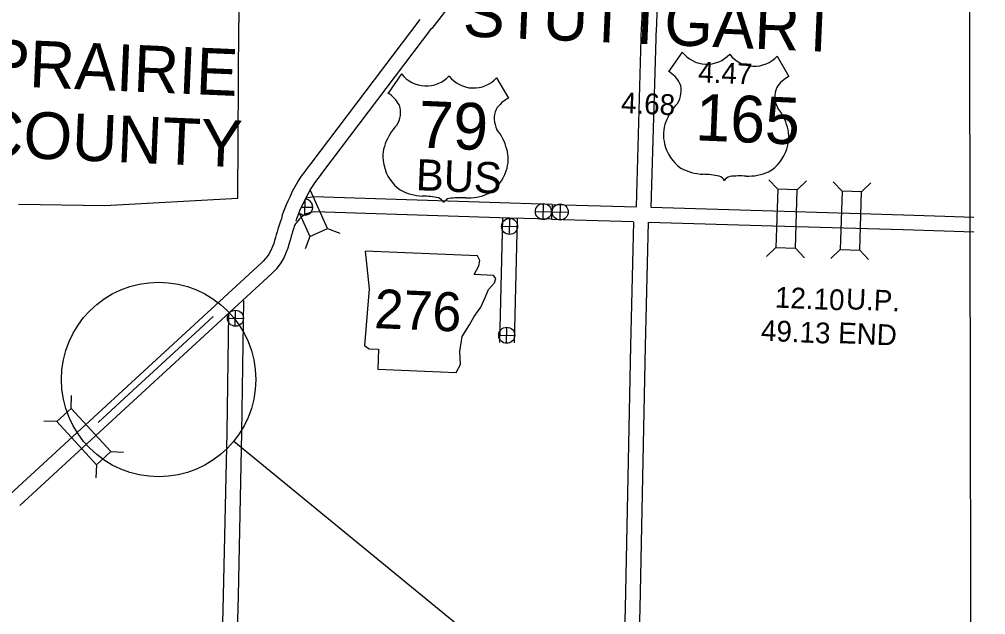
# Model space of a CAD drawing. Extents: x 1196286 to 1268366, y 2040822 to 2082115.
# Drawn here: x 1203681 to 1207611, y 2076830 to 2079249 of the extents above; entities that cross this region are included whole.
import ezdxf

# ---------------------------------------------------------------- set-up
doc = ezdxf.new("R2010")
doc.units = 0
for name, color, linetype in [('55', 7, 'Continuous'), ('Level 100', 7, 'Continuous'), ('Level 70', 7, 'Continuous'), ('Level 78', 7, 'Continuous'), ('Level 8', 7, 'Continuous'), ('Level 80', 7, 'Continuous'), ('Level 82', 7, 'Continuous'), ('Level 84', 7, 'Continuous'), ('Level 87', 7, 'Continuous'), ('Level 95', 7, 'Continuous'), ('Level 96', 7, 'Continuous'), ('Level 97', 7, 'Continuous'), ('Level 98', 7, 'Continuous')]:
    doc.layers.add(name, color=color, linetype=linetype)

msp = doc.modelspace()

# ---------------------------------------------------------------- linework, layer by layer
at = {"layer": '55'}
for points in [[(1207474.9, 2081607.9), (1206837.9, 2081629.8), (1206310.3, 2081646.8), (1205782.4, 2081667.1), (1205202.6, 2081688.7), (1204632, 2081707.9), (1204616.8, 2081158.3), (1204597.1, 2080598.6), (1204583.7, 2080115.1), (1204568.5, 2079583.1), (1204573.6, 2079234.1)], [(1203677.3, 2078498.2), (1204029.1, 2078492.6), (1204569.7, 2078521.8), (1204573.6, 2079234.1)]]:
    msp.add_lwpolyline(points, dxfattribs=at)
at = {"layer": 'Level 100'}
for p, q in [((1204841.8, 2078453.2), (1204843.1, 2078518.3)), ((1204831.6, 2078486), (1204875, 2078485.1)), ((1205811.8, 2078435), (1205813.1, 2078500.1)), ((1205880.3, 2078433.6), (1205881.6, 2078498.7)), ((1205674.3, 2078375), (1205675.6, 2078440.1)), ((1205779.9, 2078468.2), (1205845, 2078466.9)), ((1205848.4, 2078466.8), (1205913.5, 2078465.5)), ((1205642.4, 2078408.2), (1205707.5, 2078406.9)), ((1204559.5, 2078001.8), (1204560.8, 2078066.9)), ((1204527.6, 2078035), (1204592.7, 2078033.7)), ((1205630.8, 2077965.6), (1205695.9, 2077964.3)), ((1205662.7, 2077932.4), (1205664, 2077997.5))]:
    msp.add_line(p, q, dxfattribs=at)
for centre in [(1205812.5, 2078467.5), (1205880.9, 2078466.1), (1205675, 2078407.6), (1204560.2, 2078034.3), (1205663.3, 2077965)]:
    msp.add_circle(centre, 32.6, dxfattribs=at)
msp.add_arc((1204842.4, 2078485.7), 32.6, 230.3311, 84.3995, dxfattribs=at)
at = {"layer": 'Level 78'}
msp.add_lwpolyline([(1205088.3, 2078307.1), (1205104.6, 2078154), (1205084.6, 2077923.7), (1205104.3, 2077910.2), (1205142.4, 2077908.6), (1205138.9, 2077827.4), (1205458.3, 2077813.8), (1205475, 2077846.1), (1205472.2, 2077899.5), (1205482.4, 2077960), (1205512.3, 2078007), (1205531.6, 2078041.8), (1205558.6, 2078078.7), (1205575.5, 2078118.6), (1205589.6, 2078151), (1205613.6, 2078177.9), (1205619.5, 2078195.5), (1205609.9, 2078208.6), (1205531.3, 2078211.9), (1205550.5, 2078246.7), (1205554.1, 2078269.4), (1205544.3, 2078287.4)], close=True, dxfattribs=at)
at = {"layer": 'Level 8'}
msp.add_line((1204553.5, 2077535), (1208376.7, 2074405.8), dxfattribs=at)
msp.add_lwpolyline([(1196285.8, 2082114.9), (1207540.7, 2082114.9), (1207563, 2069523.3), (1196285.8, 2069523.3)], close=True, dxfattribs=at)
msp.add_lwpolyline([(1204002, 2077610.5), (1204109.1, 2077709), (1204396.5, 2077973.5), (1204469.5, 2078041.3)], dxfattribs=at)
msp.add_circle((1204247.6, 2077785.3), 395.3, dxfattribs=at)
at = {"layer": 'Level 80'}
for p, q in [((1206377.4, 2079116), (1206322.1, 2079038)), ((1206763.1, 2079099.5), (1206811.5, 2079017)), ((1205236, 2079027.3), (1205180.7, 2078949.3)), ((1205621.8, 2079010.8), (1205670.2, 2078928.3))]:
    msp.add_line(p, q, dxfattribs=at)
for centre, radius, start, end in [((1206477.5, 2079193.1), 126.4, 217.623, 317.2181), ((1206670, 2079184.9), 126.4, 217.8778, 317.4729), ((1205336.1, 2079104.5), 126.4, 217.623, 317.2181), ((1206249.3, 2078924.4), 134.9, 28.3289, 57.5362), ((1205528.6, 2079096.2), 126.4, 217.8778, 317.4729), ((1206280.5, 2078958.7), 92.5, 326.3584, 18.7587), ((1206874.3, 2078897.7), 134.9, 117.5597, 146.767), ((1205108, 2078835.7), 134.9, 28.3289, 57.5362), ((1206846.2, 2078934.5), 92.5, 156.3372, 208.7375), ((1205733, 2078809), 134.9, 117.5597, 146.767), ((1206514, 2078759), 215.7, 136.5044, 160.2393), ((1205139.1, 2078870), 92.5, 326.3584, 18.7587), ((1205704.9, 2078845.8), 92.5, 156.3372, 208.7375), ((1206596.5, 2078755.4), 215.7, 14.8566, 38.5915), ((1206443.6, 2078779.7), 142.6, 158.5056, 194.9298), ((1205372.6, 2078670.3), 215.7, 136.5044, 160.2393), ((1205455.1, 2078666.7), 215.7, 14.8566, 38.5915), ((1206668.4, 2078770), 142.6, 340.1661, 16.5903), ((1205302.2, 2078691), 142.6, 158.5056, 194.9298), ((1205527.1, 2078681.4), 142.6, 340.1661, 16.5903), ((1206466.8, 2078779.1), 165, 192.6554, 234.6791), ((1206645.2, 2078771.4), 165, 300.4168, 342.4405), ((1205325.4, 2078690.4), 165, 192.6554, 234.6791), ((1205503.9, 2078682.8), 165, 300.4168, 342.4405), ((1206472.1, 2078830.9), 211.8, 241.625, 267.1258), ((1206451.3, 2078231.5), 388, 78.7421, 88.5018), ((1206514.7, 2078576.9), 37.2, 25.5822, 70.5343), ((1206580.2, 2078574.1), 37.2, 104.5616, 149.5137), ((1206613.8, 2078224.5), 388, 86.5941, 96.3538), ((1206644.4, 2078823.5), 211.8, 267.9701, 293.4709), ((1205330.7, 2078742.2), 211.8, 241.625, 267.1258), ((1205310, 2078142.8), 388, 78.7421, 88.5018), ((1205373.3, 2078488.2), 37.2, 25.5822, 70.5343), ((1205438.9, 2078485.4), 37.2, 104.5616, 149.5137), ((1205472.5, 2078135.8), 388, 86.5941, 96.3538), ((1205503, 2078734.8), 211.8, 267.9701, 293.4709)]:
    msp.add_arc(centre, radius, start, end, dxfattribs=at)
at = {"layer": 'Level 84'}
for points in [[(1206222.9, 2079653.8), (1206076.9, 2079554.7), (1206042, 2079537.7), (1206024.4, 2079533.2), (1206007.5, 2079529.9), (1205989.9, 2079529.5), (1205962, 2079530.1), (1205937.7, 2079530.6), (1205718.3, 2079537.8), (1205668.6, 2079538.7), (1205657.3, 2079537.3), (1205642.7, 2079535.6), (1205627.8, 2079529.9), (1205616.3, 2079525.1), (1205605, 2079518.8), (1205594.8, 2079512.6), (1205585.3, 2079504.7), (1205572.1, 2079488.7), (1205561, 2079473.6), (1205358.7, 2079212.3)], [(1206217.3, 2079437.4), (1206212.1, 2079219.2)], [(1206277.2, 2079431.3), (1206272.1, 2079217.8)], [(1204748.1, 2078437.4), (1204750.9, 2078455.9), (1204759.6, 2078476.3), (1204767.5, 2078496), (1204774.9, 2078511.8), (1204782.2, 2078527.8), (1204792.7, 2078550), (1204814.1, 2078588.1), (1204829.4, 2078611.3), (1204843.1, 2078630.2), (1204853.8, 2078644.5), (1204868.4, 2078663.6), (1205311.1, 2079248.7)], [(1204807.4, 2078428.4), (1204809.1, 2078439.4), (1204815, 2078453.3), (1204822.6, 2078472.1), (1204829.4, 2078486.7), (1204836.6, 2078502.4), (1204846.1, 2078522.4), (1204865.3, 2078556.8), (1204878.8, 2078577.2), (1204891.5, 2078594.7), (1204901.6, 2078608.3), (1204916.1, 2078627.2), (1205358.9, 2079212.5)], [(1206190.6, 2078487.7), (1206212.1, 2079219.4)], [(1206250.5, 2078483.9), (1206272.1, 2079217.6)], [(1205847.8, 2078496.5), (1205677.3, 2078501.3), (1204876.9, 2078527.2), (1204862.9, 2078524.4), (1204853, 2078522.9), (1204845.5, 2078520.8)], [(1205847.8, 2078496.5), (1205846, 2078436.5)], [(1204746.9, 2078438), (1204744.6, 2078433.5), (1204739.6, 2078415.9), (1204735.2, 2078403.8), (1204733, 2078396), (1204729.7, 2078385.5), (1204726.2, 2078372.7), (1204722.8, 2078362.5), (1204719, 2078350.6), (1204715.6, 2078337.7), (1204710.9, 2078325.5), (1204704.4, 2078309.6), (1204695.5, 2078294.9), (1204693.5, 2078290.6), (1204689.3, 2078285.4), (1204685.7, 2078280), (1204682.6, 2078276.6), (1204672.4, 2078266.1), (1204665.8, 2078258.9), (1203642.8, 2077318.1)], [(1205846, 2078436.5), (1205675.5, 2078441.3), (1204881.9, 2078467), (1204873.3, 2078465.3), (1204865.5, 2078464.1), (1204857.5, 2078461.9), (1204849.4, 2078458.9), (1204842.2, 2078455.1), (1204838.6, 2078453.5), (1204835.4, 2078451), (1204829.2, 2078445.9), (1204820, 2078437.8), (1204814.8, 2078431.7), (1204806.8, 2078421.3), (1204803.5, 2078417.1), (1204802.4, 2078414.6), (1204800.7, 2078411.3), (1204796.7, 2078397.5), (1204792.4, 2078385.5), (1204790.5, 2078378.9), (1204787.3, 2078368.4), (1204783.6, 2078355.3), (1204779.9, 2078344.1), (1204776.7, 2078333.8), (1204772.8, 2078319.2), (1204766.7, 2078303.3), (1204758.1, 2078282.4), (1204748.6, 2078266.8), (1204745, 2078258.9), (1204737.5, 2078249.6), (1204732.9, 2078242.8), (1204726.4, 2078235.7), (1204716, 2078224.8), (1204708.1, 2078216.4), (1203683.5, 2077274)], [(1206179, 2078426.6), (1206167, 2077921.6), (1206155.7, 2077388.3), (1206144.6, 2076856.6), (1206130.5, 2076321.7)], [(1206239, 2078425.3), (1206227, 2077920.3), (1206215.7, 2077387), (1206204.6, 2076855.2), (1206190.5, 2076320.2)]]:
    msp.add_lwpolyline(points, dxfattribs=at)
at = {"layer": 'Level 87'}
for points in [[(1205847.8, 2078496.5), (1206190.6, 2078486.8)], [(1206250.9, 2078485), (1206747.3, 2078470.4), (1207277.2, 2078454.4), (1207444.7, 2078449.1)], [(1205645.7, 2078441.3), (1205633.5, 2077936.4)], [(1205705.7, 2078439.9), (1205693.4, 2077934.9)], [(1205846, 2078436.5), (1206177.9, 2078427.1)], [(1207444.7, 2078449.1), (1207563, 2078445.4)], [(1206239.5, 2078425.3), (1206745.5, 2078410.4), (1207275.4, 2078394.4), (1207442.8, 2078389.2)], [(1207442.8, 2078389.2), (1207563, 2078385.3)]]:
    msp.add_lwpolyline(points, dxfattribs=at)
at = {"layer": 'Level 95'}
for points in [[(1204593, 2078107), (1204584.6, 2077570), (1204570.7, 2076906), (1204556.3, 2076363.1), (1204544.8, 2075860.8), (1205107.9, 2075845.4), (1205097.7, 2075281.9), (1205095.7, 2075276.4), (1205091.8, 2075262.6), (1205078.9, 2075255.9), (1205075.1, 2075253.8), (1205064.6, 2075250.9), (1205062.1, 2075251), (1205049.3, 2074679.6)], [(1204532.2, 2078054.2), (1204524.6, 2077571.1), (1204510.7, 2076907.4), (1204496.4, 2076364.6), (1204483.4, 2075802.5), (1205046.8, 2075787), (1205038.2, 2075311), (1205003.5, 2075310.7), (1204989.3, 2074680.9)]]:
    msp.add_lwpolyline(points, dxfattribs=at)
at = {"layer": 'Level 98'}
for p, q in [((1206765.7, 2078558.7), (1206729.5, 2078597.1)), ((1206844.9, 2078556.3), (1206883.3, 2078592.5)), ((1204935, 2078398.4), (1204865.7, 2078553.1)), ((1207027.3, 2078550.8), (1206991.1, 2078589.2)), ((1207106.5, 2078548.4), (1207144.9, 2078584.6)), ((1204820.5, 2078460.2), (1204862.8, 2078366)), ((1204862.8, 2078366), (1204935, 2078398.4)), ((1204935, 2078398.4), (1204984.4, 2078379.6)), ((1204862.8, 2078366), (1204844, 2078316.6)), ((1206758.5, 2078321.2), (1206720.1, 2078285)), ((1206837.7, 2078318.8), (1206873.9, 2078280.3)), ((1207020.2, 2078313.3), (1206981.7, 2078277.1)), ((1207099.3, 2078310.9), (1207135.5, 2078272.4)), ((1203891.7, 2077667.7), (1203893.9, 2077720.4)), ((1203833.4, 2077614.1), (1203780.7, 2077616.3)), ((1204052.6, 2077492.8), (1204105.3, 2077490.6)), ((1203994.3, 2077439.2), (1203992.1, 2077386.4))]:
    msp.add_line(p, q, dxfattribs=at)
for points in [[(1206837.7, 2078318.8), (1206844.9, 2078556.3), (1206765.7, 2078558.7), (1206758.5, 2078321.2)], [(1207027.3, 2078550.8), (1207020.2, 2078313.3), (1207099.3, 2078310.9), (1207106.5, 2078548.4)], [(1204052.6, 2077492.8), (1203891.7, 2077667.7), (1203833.4, 2077614.1), (1203994.3, 2077439.2)]]:
    msp.add_lwpolyline(points, close=True, dxfattribs=at)

# ---------------------------------------------------------------- texts
at = {"layer": 'Level 70'}
msp.add_text('STUTTGART', height=190.08, rotation=357.548, dxfattribs=at).set_placement((1205483, 2079180.2))
at = {"layer": 'Level 78'}
msp.add_text('276', height=158.4, rotation=357.548, dxfattribs=at).set_placement((1205122.8, 2077994.6))
at = {"layer": 'Level 80'}
for s, height, p in [('165', 190.08, (1206428.2, 2078757.7)), ('79', 190.08, (1205300.9, 2078728.5)), ('BUS', 126.72, (1205292.3, 2078554.9))]:
    msp.add_text(s, height=height, rotation=357.548, dxfattribs=at).set_placement(p)
at = {"layer": 'Level 82'}
msp.add_text('4.47', height=84.48, rotation=357.548, dxfattribs=at).set_placement((1206441, 2078993.4))
at = {"layer": 'Level 96'}
for s, p in [('PRAIRIE', (1203550.2, 2078980.8)), ('COUNTY', (1203511.3, 2078693.2))]:
    msp.add_text(s, height=190.08, rotation=357.548, dxfattribs=at).set_placement(p)
at = {"layer": 'Level 97'}
for s, p in [('4.68', (1206126.9, 2078868.4)), ('12.10', (1206753.1, 2078077.9)), ('U.P.', (1207042, 2078071.2)), ('49.13', (1206696.1, 2077943.2)), ('END', (1207010.1, 2077933.4))]:
    msp.add_text(s, height=84.48, rotation=357.548, dxfattribs=at).set_placement(p)

doc.saveas('drawing.dxf')
